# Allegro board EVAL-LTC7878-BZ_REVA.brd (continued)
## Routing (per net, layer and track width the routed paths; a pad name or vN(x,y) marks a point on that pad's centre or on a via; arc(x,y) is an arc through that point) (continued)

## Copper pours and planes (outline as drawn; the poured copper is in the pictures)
SGND on TOP: 89.74,137.54 89.77,137.53 89.79,137.49 89.79,136.83 89.77,136.79 89.74,136.78 88.57,136.78 88.53,136.79 88.52,136.83 88.52,137.49 88.53,137.53 88.57,137.54
SGND on TOP: 89.74,15.62 89.77,15.61 89.79,15.57 89.79,14.91 89.77,14.87 89.74,14.86 88.57,14.86 88.53,14.87 88.52,14.91 88.52,15.57 88.53,15.61 88.57,15.62
SGND on TOP: 102.58,72.26 104.43,72.26
SGND on TOP: 103.3,10.67 103.27,10.68 103.25,10.72 103.25,13.92 103.27,13.96 103.3,13.97 104.47,13.97 104.51,13.96 104.52,13.92 104.52,13.26 104.51,13.22 104.47,13.21 104.06,13.21 104.03,13.19 104.01,13.16 104.01,10.72 104,10.68 103.96,10.67
SGND on TOP: 98.98,133.84 98.99,133.85 99.01,133.86 99.39,133.86 99.43,133.84 99.44,133.81 99.44,132 99.43,131.97 99.39,131.95 98.73,131.95 98.69,131.97 98.68,132 98.68,133.53 98.68,133.54 98.69,133.56
SGND on TOP: 102.58,11.3 104.43,11.3
SGND on TOP: 103.25,141.94 103.27,141.97 103.3,141.99 105.23,141.99 105.27,141.97 105.28,141.94 105.28,139.19 104.14,139.19 104.14,137.16 103.3,137.16 103.27,137.18 103.25,137.21 103.25,139.9 103.27,139.94 103.3,139.95 104.9,139.95 104.9,141.22 103.3,141.22 103.27,141.24 103.25,141.28
SGND on TOP: 96.65,72.85 96.66,72.88 96.7,72.9 97.36,72.9 97.39,72.88 97.41,72.85 97.41,71.68 97.39,71.64 97.36,71.63 96.7,71.63 96.66,71.64 96.65,71.68
SGND on TOP: 103.3,254.51 103.27,254.52 103.25,254.56 103.25,257.76 103.27,257.8 103.3,257.81 104.47,257.81 104.51,257.8 104.52,257.76 104.52,257.1 104.51,257.06 104.47,257.05 104.06,257.05 104.03,257.03 104.01,257 104.01,254.56 104,254.52 103.96,254.51
SGND on TOP: 98.98,194.8 98.99,194.81 99.01,194.82 99.39,194.82 99.43,194.8 99.44,194.77 99.44,192.96 99.43,192.93 99.39,192.91 98.73,192.91 98.69,192.93 98.68,192.96 98.68,194.49 98.68,194.5 98.69,194.52
SGND on TOP: 103.25,80.98 103.27,81.01 103.3,81.03 105.23,81.03 105.27,81.01 105.28,80.98 105.28,78.23 104.14,78.23 104.14,76.2 103.3,76.2 103.27,76.22 103.25,76.25 103.25,78.94 103.27,78.98 103.3,78.99 104.9,78.99 104.9,80.26 103.3,80.26 103.27,80.28 103.25,80.32
SGND on TOP: 90.88,135.38 90.92,135.37 90.93,135.33 90.93,134.54 90.92,134.51 90.88,134.49 89.2,134.49 89.17,134.51 89.15,134.54 89.15,135.33 89.17,135.37 89.2,135.38
SGND on TOP: 96.65,255.73 96.66,255.76 96.7,255.78 97.36,255.78 97.39,255.76 97.41,255.73 97.41,254.56 97.39,254.52 97.36,254.51 96.7,254.51 96.66,254.52 96.65,254.56
SGND on TOP: 89.74,259.46 89.77,259.45 89.79,259.41 89.79,258.75 89.77,258.71 89.74,258.7 88.57,258.7 88.53,258.71 88.52,258.75 88.52,259.41 88.53,259.45 88.57,259.46
SGND on TOP: 96.65,11.89 96.66,11.92 96.7,11.94 97.36,11.94 97.39,11.92 97.41,11.89 97.41,10.72 97.39,10.68 97.36,10.67 96.7,10.67 96.66,10.68 96.65,10.72
SGND on TOP: 98.98,11.92 98.99,11.93 99.01,11.94 99.39,11.94 99.43,11.92 99.44,11.89 99.44,10.08 99.43,10.05 99.39,10.03 98.73,10.03 98.69,10.05 98.68,10.08 98.68,11.61 98.68,11.62 98.69,11.64
SGND on TOP: 90.88,257.3 90.92,257.29 90.93,257.25 90.93,256.46 90.92,256.43 90.88,256.41 89.2,256.41 89.17,256.43 89.15,256.46 89.15,257.25 89.17,257.29 89.2,257.3
SGND on TOP: 103.25,263.86 103.27,263.89 103.3,263.91 105.23,263.91 105.27,263.89 105.28,263.86 105.28,261.11 104.14,261.11 104.14,259.08 103.3,259.08 103.27,259.1 103.25,259.13 103.25,261.82 103.27,261.86 103.3,261.87 104.6,261.87 104.63,261.89 104.65,261.92 104.65,263.09 104.63,263.13 104.6,263.14 103.3,263.14 103.27,263.16 103.25,263.2
SGND on TOP: 89.74,76.58 89.77,76.57 89.79,76.53 89.79,75.87 89.77,75.83 89.74,75.82 88.57,75.82 88.53,75.83 88.52,75.87 88.52,76.53 88.53,76.57 88.57,76.58
SGND on TOP: 103.3,193.55 103.27,193.56 103.25,193.6 103.25,196.8 103.27,196.84 103.3,196.85 104.47,196.85 104.51,196.84 104.52,196.8 104.52,196.14 104.51,196.1 104.47,196.09 104.06,196.09 104.03,196.07 104.01,196.04 104.01,193.6 104,193.56 103.96,193.55
SGND on TOP: 102.58,255.14 104.43,255.14
SGND on TOP: 96.65,194.77 96.66,194.8 96.7,194.82 97.36,194.82 97.39,194.8 97.41,194.77 97.41,193.6 97.39,193.56 97.36,193.55 96.7,193.55 96.66,193.56 96.65,193.6
SGND on TOP: 90.88,13.46 90.92,13.45 90.93,13.41 90.93,12.62 90.92,12.59 90.88,12.57 89.2,12.57 89.17,12.59 89.15,12.62 89.15,13.41 89.17,13.45 89.2,13.46
SGND on TOP: 98.98,72.88 98.99,72.89 99.01,72.9 99.39,72.9 99.43,72.88 99.44,72.85 99.44,71.04 99.43,71.01 99.39,70.99 98.73,70.99 98.69,71.01 98.68,71.04 98.68,72.57 98.68,72.58 98.69,72.6
SGND on TOP: 102.58,133.22 104.43,133.22
SGND on TOP: 103.3,132.59 103.27,132.6 103.25,132.64 103.25,135.84 103.27,135.88 103.3,135.89 104.47,135.89 104.51,135.88 104.52,135.84 104.52,135.18 104.51,135.14 104.47,135.13 104.06,135.13 104.03,135.11 104.01,135.08 104.01,132.64 104,132.6 103.96,132.59
SGND on TOP: 89.74,198.5 89.77,198.49 89.79,198.45 89.79,197.79 89.77,197.75 89.74,197.74 88.57,197.74 88.53,197.75 88.52,197.79 88.52,198.45 88.53,198.49 88.57,198.5
SGND on TOP: 98.98,255.76 98.99,255.77 99.01,255.78 99.39,255.78 99.43,255.76 99.44,255.73 99.44,253.92 99.43,253.89 99.39,253.87 98.73,253.87 98.69,253.89 98.68,253.92 98.68,255.45 98.68,255.46 98.69,255.48
SGND on TOP: 103.25,202.9 103.27,202.93 103.3,202.95 105.23,202.95 105.27,202.93 105.28,202.9 105.28,200.15 104.14,200.15 104.14,198.12 103.3,198.12 103.27,198.14 103.25,198.17 103.25,200.86 103.27,200.9 103.3,200.91 104.9,200.91 104.9,202.18 103.3,202.18 103.27,202.2 103.25,202.24
SGND on TOP: 102.58,194.18 104.43,194.18
SGND on TOP: 90.88,74.42 90.92,74.41 90.93,74.37 90.93,73.58 90.92,73.55 90.88,73.53 89.2,73.53 89.17,73.55 89.15,73.58 89.15,74.37 89.17,74.41 89.2,74.42
SGND on TOP: 90.88,196.34 90.92,196.33 90.93,196.29 90.93,195.5 90.92,195.47 90.88,195.45 89.2,195.45 89.17,195.47 89.15,195.5 89.15,196.29 89.17,196.33 89.2,196.34
SGND on TOP: 103.25,20.02 103.27,20.05 103.3,20.07 105.23,20.07 105.27,20.05 105.28,20.02 105.28,17.27 104.14,17.27 104.14,15.24 103.3,15.24 103.27,15.26 103.25,15.29 103.25,17.98 103.27,18.02 103.3,18.03 104.9,18.03 104.9,19.3 103.3,19.3 103.27,19.32 103.25,19.36
SGND on TOP: 96.65,133.81 96.66,133.84 96.7,133.86 97.36,133.86 97.39,133.84 97.41,133.81 97.41,132.64 97.39,132.6 97.36,132.59 96.7,132.59 96.66,132.6 96.65,132.64
SGND on TOP: 103.3,71.63 103.27,71.64 103.25,71.68 103.25,74.88 103.27,74.92 103.3,74.93 104.47,74.93 104.51,74.92 104.52,74.88 104.52,74.22 104.51,74.18 104.47,74.17 104.06,74.17 104.03,74.15 104.01,74.12 104.01,71.68 104,71.64 103.96,71.63
SGND on BOTTOM: 108.97,84.33 108.97,66.55 83.57,66.55 83.57,84.33
SGND on BOTTOM: 108.97,23.24 108.97,5.71 83.57,5.71 83.57,23.24
SGND on BOTTOM: 109.09,188.59 83.57,188.59 83.57,206.12 109.09,206.12
SGND on BOTTOM: 109.09,249.56 83.57,249.56 83.57,267.21 109.09,267.21
SGND on BOTTOM: 108.97,127.64 83.44,127.64 83.44,145.29 108.97,145.29
SGND on LAYER_2: 82.3,307.47 82.3,8.64 113.41,8.64 113.41,307.47
SGND on LAYER_3: 109.09,249.56 83.57,249.56 83.57,269.88 109.09,269.88
SGND on LAYER_3: 83.44,127.64 83.44,147.96 108.97,147.96 108.97,127.64
SGND on LAYER_3: 109.09,188.72 83.57,188.72 83.57,208.91 109.09,208.91
SGND on LAYER_3: 83.57,5.71 83.57,26.04 108.97,26.04 108.97,5.71
SGND on LAYER_3: 83.57,66.67 83.57,87 108.97,87 108.97,66.67
SGND on LAYER_4: 95.25,20.83 94.11,19.68 94.11,16.89 97.79,16.89 98.04,17.14 98.04,20.83
SGND on LAYER_4: 95.89,265.05 94.11,263.27 94.11,260.73 97.85,260.73 98.04,260.92 98.04,265.05
SGND on LAYER_4: 95.63,143 94.11,141.48 94.11,138.81 97.79,138.81 98.04,139.06 98.04,143
SGND on LAYER_4: 95.89,203.96 94.23,202.31 94.23,199.77 97.79,199.77 98.04,200.03 98.04,203.96
SGND on LAYER_4: 95.89,82.17 94.11,80.39 94.11,77.85 97.79,77.85 98.04,78.11 98.04,82.17
SGND on LAYER_5: 114.3,273.62 114.3,10.6 89.73,10.6 89.73,273.62
SGND on LAYER_6: 100.33,259.71 92.84,259.71 92.84,268.86 100.33,268.86
SGND on LAYER_6: 100.33,207.9 100.33,198.75 92.84,198.75 92.84,207.9
SGND on LAYER_6: 100.33,15.88 92.84,15.88 92.84,25.02 100.33,25.02
SGND on LAYER_6: 100.33,146.81 100.33,137.79 92.84,137.79 92.84,146.81
SGND on LAYER_6: 100.33,86.11 100.33,77.22 92.84,77.22 92.84,86.11
VIN on TOP: 88.27,13.41 88.28,13.45 88.32,13.46 88.72,13.46 88.76,13.45 88.77,13.41 88.77,12.24 88.76,12.21 88.72,12.19 88.32,12.19 88.28,12.21 88.27,12.24
VIN on TOP: 88.03,143.64 88.01,143.64 88,143.65 87.9,143.75 87.89,143.77 87.88,143.79 87.88,144.35 87.9,144.38 87.93,144.4 89.1,144.4 89.14,144.38 89.15,144.35 89.15,143.69 89.14,143.65 89.1,143.64
VIN on TOP: 88.27,74.37 88.28,74.41 88.32,74.42 88.72,74.42 88.76,74.41 88.77,74.37 88.77,73.2 88.76,73.17 88.72,73.15 88.32,73.15 88.28,73.17 88.27,73.2
VIN on TOP: 88.03,204.6 88.01,204.6 88,204.61 87.9,204.71 87.89,204.73 87.88,204.75 87.88,205.31 87.9,205.34 87.93,205.36 89.1,205.36 89.14,205.34 89.15,205.31 89.15,204.65 89.14,204.61 89.1,204.6
VIN on TOP: 88.27,257.25 88.28,257.29 88.32,257.3 88.72,257.3 88.76,257.29 88.77,257.25 88.77,256.08 88.76,256.05 88.72,256.03 88.32,256.03 88.28,256.05 88.27,256.08
VIN on TOP: 88.27,196.29 88.28,196.33 88.32,196.34 88.72,196.34 88.76,196.33 88.77,196.29 88.77,195.12 88.76,195.09 88.72,195.07 88.32,195.07 88.28,195.09 88.27,195.12
VIN on TOP: 88.03,82.68 88.01,82.68 88,82.69 87.9,82.79 87.89,82.81 87.88,82.83 87.88,83.39 87.9,83.42 87.93,83.44 89.1,83.44 89.14,83.42 89.15,83.39 89.15,82.73 89.14,82.69 89.1,82.68
VIN on TOP: 88.27,135.33 88.28,135.37 88.32,135.38 88.72,135.38 88.76,135.37 88.77,135.33 88.77,134.16 88.76,134.13 88.72,134.11 88.32,134.11 88.28,134.13 88.27,134.16
VIN on TOP: 125.35,129.54 125.35,126.11 128.91,126.11 130.05,127.25 132.84,127.25 133.48,127.89 134.37,127.89 134.62,128.14 136.4,128.14 136.46,128.21 136.46,128.71 136.4,128.78 135.76,128.78 135,129.54
VIN on TOP: 14.48,305.56 79.12,305.56 79.12,287.02 39.5,287.02 39.5,244.6 79.12,244.6 79.12,226.06 39.5,226.06 39.5,183.64 79.12,183.64 79.12,165.1 39.5,165.1 39.5,122.68 79.12,122.68 79.12,104.14 39.5,104.14 39.5,61.72 79.12,61.72 79.12,43.18 39.5,43.18 39.5,43.15 14.91,43.15 14.91,152.65 2.67,152.65 2.67,200.66 14.48,200.66
VIN on TOP: 88.03,21.72 88.01,21.72 88,21.73 87.9,21.83 87.89,21.85 87.88,21.87 87.88,22.43 87.9,22.46 87.93,22.48 89.1,22.48 89.14,22.46 89.15,22.43 89.15,21.77 89.14,21.73 89.1,21.72
VIN on TOP: 88.03,265.56 88.01,265.56 88,265.57 87.9,265.67 87.89,265.69 87.88,265.71 87.88,266.27 87.9,266.3 87.93,266.32 89.1,266.32 89.14,266.3 89.15,266.27 89.15,265.61 89.14,265.57 89.1,265.56
VIN on BOTTOM: 14.48,305.56 79.07,305.56 79.11,305.55 79.12,305.51 79.12,287.07 79.11,287.03 79.07,287.02 39.5,287.02 39.5,244.6 79.12,244.6 79.12,226.11 79.11,226.07 79.07,226.06 39.5,226.06 39.5,183.64 79.12,183.64 79.12,165.15 79.11,165.11 79.07,165.1 39.5,165.1 39.5,122.68 79.12,122.68 79.12,104.14 39.5,104.14 39.5,61.72 79.12,61.72 79.12,43.18 39.5,43.18 39.5,43.15 14.91,43.15 14.91,152.65 2.67,152.65 2.67,200.66 14.48,200.66
VIN on LAYER_2: 2.54,202.56 2.54,150.5 13.97,150.5 13.97,8.64 79.38,8.64 79.38,31.75 71.12,31.75 71.12,41.91 79.38,41.91 79.38,92.71 71.12,92.71 71.12,102.23 79.38,102.23 79.38,153.67 70.99,153.67 70.99,163.19 79.38,163.19 79.38,214.63 70.99,214.63 70.99,224.16 79.38,224.16 79.38,275.59 71.12,275.59 71.12,285.12 79.38,285.12 79.38,307.47 13.97,307.47 13.97,202.56
VIN on LAYER_3, LAYER_7: 79.38,225.3 79.38,233.93 71.63,233.93 71.63,225.3
VIN on LAYER_3, LAYER_7: 79.38,42.42 79.38,51.05 71.63,51.05 71.63,42.42
VIN on LAYER_3, LAYER_7: 79.38,286.26 79.38,294.89 71.63,294.89 71.63,286.26
VIN on LAYER_3, LAYER_7: 79.38,103.38 79.38,112.01 71.63,112.01 71.63,103.38
VIN on LAYER_3, LAYER_7: 79.38,164.34 79.38,172.97 71.63,172.97 71.63,164.34
VIN on LAYER_4, LAYER_5, LAYER_6: 79.38,163.19 79.38,172.21 71.63,172.21 71.63,163.19
VIN on LAYER_4, LAYER_5, LAYER_6: 79.38,224.16 79.38,233.17 71.63,233.17 71.63,224.16
VIN on LAYER_4, LAYER_5, LAYER_6: 79.38,102.23 79.38,111.25 71.63,111.25 71.63,102.23
VIN on LAYER_4, LAYER_5, LAYER_6: 79.38,285.12 79.38,294.13 71.63,294.13 71.63,285.12
VIN on LAYER_4, LAYER_5, LAYER_6: 79.38,41.27 79.38,50.29 71.63,50.29 71.63,41.27
DRVCC_1 on TOP: 91.26,263.21 91.3,263.19 91.31,263.16 91.31,262.62 91.3,262.59 91.26,262.57 90.09,262.57 90.06,262.59 90.04,262.62 90.04,263.16 90.06,263.19 90.09,263.21
DRVCC_1 on TOP: 91.26,268.1 91.3,268.08 91.31,268.05 91.31,267.39 91.3,267.35 91.26,267.33 89.84,267.33 89.8,267.35 89.79,267.39 89.79,268.05 89.8,268.08 89.84,268.1
DRVCC_1 on TOP: 77.31,266.95 79.16,266.95
DRVCC_1 on TOP: 92.02,255.4 92.06,255.38 92.08,255.35 92.08,254.69 92.06,254.65 92.02,254.63 90.86,254.63 90.82,254.65 90.81,254.69 90.81,255.35 90.82,255.38 90.86,255.4
DRVCC_2 on TOP: 77.31,205.99 79.16,205.99
DRVCC_2 on TOP: 91.26,207.14 91.3,207.12 91.31,207.09 91.31,206.43 91.3,206.39 91.26,206.38 89.84,206.38 89.8,206.39 89.79,206.43 89.79,207.09 89.8,207.12 89.84,207.14
DRVCC_2 on TOP: 91.26,202.25 91.3,202.23 91.31,202.2 91.31,201.66 91.3,201.63 91.26,201.61 90.09,201.61 90.06,201.63 90.04,201.66 90.04,202.2 90.06,202.23 90.09,202.25
DRVCC_2 on TOP: 92.02,194.44 92.06,194.42 92.08,194.39 92.08,193.73 92.06,193.69 92.02,193.68 90.86,193.68 90.82,193.69 90.81,193.73 90.81,194.39 90.82,194.42 90.86,194.44
DRVCC_3 on TOP: 91.26,146.18 91.3,146.16 91.31,146.13 91.31,145.47 91.3,145.43 91.26,145.41 89.84,145.41 89.8,145.43 89.79,145.47 89.79,146.13 89.8,146.16 89.84,146.18
DRVCC_3 on TOP: 92.02,133.48 92.06,133.46 92.08,133.43 92.08,132.77 92.06,132.73 92.02,132.72 90.86,132.72 90.82,132.73 90.81,132.77 90.81,133.43 90.82,133.46 90.86,133.48
DRVCC_3 on TOP: 77.31,145.03 79.16,145.03
DRVCC_3 on TOP: 91.26,141.29 91.3,141.27 91.31,141.24 91.31,140.7 91.3,140.67 91.26,140.65 90.09,140.65 90.06,140.67 90.04,140.7 90.04,141.24 90.06,141.27 90.09,141.29
DRVCC_4 on TOP: 91.26,85.22 91.3,85.2 91.31,85.17 91.31,84.51 91.3,84.47 91.26,84.45 89.84,84.45 89.8,84.47 89.79,84.51 89.79,85.17 89.8,85.2 89.84,85.22
DRVCC_4 on TOP: 92.02,72.52 92.06,72.5 92.08,72.47 92.08,71.81 92.06,71.77 92.02,71.75 90.86,71.75 90.82,71.77 90.81,71.81 90.81,72.47 90.82,72.5 90.86,72.52
DRVCC_4 on TOP: 77.31,84.07 79.16,84.07
DRVCC_4 on TOP: 91.26,80.33 91.3,80.31 91.31,80.28 91.31,79.74 91.3,79.71 91.26,79.69 90.09,79.69 90.06,79.71 90.04,79.74 90.04,80.28 90.06,80.31 90.09,80.33
DRVCC_5 on TOP: 91.26,24.26 91.3,24.24 91.31,24.21 91.31,23.55 91.3,23.51 91.26,23.5 89.84,23.5 89.8,23.51 89.79,23.55 89.79,24.21 89.8,24.24 89.84,24.26
DRVCC_5 on TOP: 77.31,23.11 79.16,23.11
DRVCC_5 on TOP: 91.26,19.37 91.3,19.35 91.31,19.32 91.31,18.78 91.3,18.75 91.26,18.73 90.09,18.73 90.06,18.75 90.04,18.78 90.04,19.32 90.06,19.35 90.09,19.37
DRVCC_5 on TOP: 92.02,11.56 92.06,11.54 92.08,11.51 92.08,10.85 92.06,10.81 92.02,10.79 90.86,10.79 90.82,10.81 90.81,10.85 90.81,11.51 90.82,11.54 90.86,11.56
GROUND on TOP: 1.27,316.23 184.15,316.23 184.15,1.27 1.27,1.27 ; 10 cut-outs
GROUND on BOTTOM, LAYER_2, LAYER_4, LAYER_5, LAYER_6, LAYER_7: 1.27,316.23 184.15,316.23 184.15,1.27 1.27,1.27
GROUND on LAYER_3: 1.27,316.23 184.15,316.23 184.15,1.27 1.27,1.27
INTVCC_1 on TOP: 95.63,255.73 95.65,255.76 95.68,255.78 96.34,255.78 96.38,255.76 96.39,255.73 96.39,254.94 96.38,254.9 96.34,254.89 95.3,254.89 95.26,254.9 95.25,254.94 95.25,255.47 95.26,255.51 95.3,255.52 95.58,255.52 95.62,255.54 95.63,255.57
INTVCC_1 on TOP: 77.18,258.32 79.03,258.32
INTVCC_1 on TOP: 105.66,260.81 105.68,260.84 105.72,260.86 106.5,260.86 106.54,260.84 106.55,260.81 106.55,259.19 106.54,259.16 106.5,259.14 105.72,259.14 105.68,259.16 105.66,259.19
INTVCC_2 on TOP: 77.18,197.36 79.03,197.36
INTVCC_2 on TOP: 105.66,199.85 105.68,199.88 105.72,199.9 106.5,199.9 106.54,199.88 106.55,199.85 106.55,198.23 106.54,198.2 106.5,198.18 105.72,198.18 105.68,198.2 105.66,198.23
INTVCC_2 on TOP: 95.63,194.77 95.65,194.8 95.68,194.82 96.34,194.82 96.38,194.8 96.39,194.77 96.39,193.98 96.38,193.94 96.34,193.93 95.3,193.93 95.26,193.94 95.25,193.98 95.25,194.51 95.26,194.55 95.3,194.56 95.58,194.56 95.62,194.58 95.63,194.61
INTVCC_3 on TOP: 77.18,136.4 79.03,136.4
INTVCC_3 on TOP: 105.66,138.89 105.68,138.92 105.72,138.94 106.5,138.94 106.54,138.92 106.55,138.89 106.55,137.27 106.54,137.24 106.5,137.22 105.72,137.22 105.68,137.24 105.66,137.27
INTVCC_3 on TOP: 95.63,133.81 95.65,133.84 95.68,133.86 96.34,133.86 96.38,133.84 96.39,133.81 96.39,133.02 96.38,132.98 96.34,132.97 95.3,132.97 95.26,132.98 95.25,133.02 95.25,133.55 95.26,133.59 95.3,133.6 95.58,133.6 95.62,133.62 95.63,133.65
INTVCC_4 on TOP: 105.66,77.93 105.68,77.96 105.72,77.98 106.5,77.98 106.54,77.96 106.55,77.93 106.55,76.31 106.54,76.28 106.5,76.26 105.72,76.26 105.68,76.28 105.66,76.31
INTVCC_4 on TOP: 77.18,75.44 79.03,75.44
INTVCC_4 on TOP: 95.63,72.85 95.65,72.88 95.68,72.9 96.34,72.9 96.38,72.88 96.39,72.85 96.39,72.06 96.38,72.02 96.34,72.01 95.3,72.01 95.26,72.02 95.25,72.06 95.25,72.59 95.26,72.63 95.3,72.64 95.58,72.64 95.62,72.66 95.63,72.69
INTVCC_5 on TOP: 77.18,14.48 79.03,14.48
INTVCC_5 on TOP: 105.66,16.97 105.68,17 105.72,17.02 106.5,17.02 106.54,17 106.55,16.97 106.55,15.35 106.54,15.32 106.5,15.3 105.72,15.3 105.68,15.32 105.66,15.35
INTVCC_5 on TOP: 95.63,11.89 95.65,11.92 95.68,11.94 96.34,11.94 96.38,11.92 96.39,11.89 96.39,11.1 96.38,11.06 96.34,11.05 95.3,11.05 95.26,11.06 95.25,11.1 95.25,11.63 95.26,11.67 95.3,11.68 95.58,11.68 95.62,11.7 95.63,11.73
ITH_1 on TOP: 115.23,252.73 117.18,252.73
ITH_1 on TOP: 97.66,255.73 97.68,255.76 97.71,255.78 98.37,255.78 98.41,255.76 98.42,255.73 98.42,253.92 98.41,253.89 98.37,253.87 97.71,253.87 97.68,253.89 97.66,253.92
ITH_1 on TOP: 98.68,257.12 98.69,257.16 98.73,257.18 99.39,257.18 99.43,257.16 99.44,257.12 99.44,256.08 99.43,256.05 99.39,256.03 98.73,256.03 98.69,256.05 98.68,256.08
ITH_2 on TOP: 97.66,194.77 97.68,194.8 97.71,194.82 98.37,194.82 98.41,194.8 98.42,194.77 98.42,192.96 98.41,192.93 98.37,192.91 97.71,192.91 97.68,192.93 97.66,192.96
ITH_2 on TOP: 115.23,191.77 117.18,191.77
ITH_2 on TOP: 98.68,196.16 98.69,196.2 98.73,196.22 99.39,196.22 99.43,196.2 99.44,196.16 99.44,195.12 99.43,195.09 99.39,195.07 98.73,195.07 98.69,195.09 98.68,195.12
ITH_3 on TOP: 98.68,135.2 98.69,135.24 98.73,135.25 99.39,135.25 99.43,135.24 99.44,135.2 99.44,134.16 99.43,134.13 99.39,134.11 98.73,134.11 98.69,134.13 98.68,134.16
ITH_3 on TOP: 115.23,130.18 117.18,130.18
ITH_3 on TOP: 97.66,133.81 97.68,133.84 97.71,133.86 98.37,133.86 98.41,133.84 98.42,133.81 98.42,132 98.41,131.97 98.37,131.95 97.71,131.95 97.68,131.97 97.66,132
ITH_4 on TOP: 97.66,72.85 97.68,72.88 97.71,72.9 98.37,72.9 98.41,72.88 98.42,72.85 98.42,71.04 98.41,71.01 98.37,70.99 97.71,70.99 97.68,71.01 97.66,71.04
ITH_4 on TOP: 98.68,74.24 98.69,74.28 98.73,74.3 99.39,74.3 99.43,74.28 99.44,74.24 99.44,73.2 99.43,73.17 99.39,73.15 98.73,73.15 98.69,73.17 98.68,73.2
ITH_4 on TOP: 115.23,69.22 117.18,69.22
ITH_5 on TOP: 97.66,11.89 97.68,11.92 97.71,11.94 98.37,11.94 98.41,11.92 98.42,11.89 98.42,10.08 98.41,10.05 98.37,10.03 97.71,10.03 97.68,10.05 97.66,10.08
ITH_5 on TOP: 98.68,13.28 98.69,13.32 98.73,13.34 99.39,13.34 99.43,13.32 99.44,13.28 99.44,12.24 99.43,12.21 99.39,12.19 98.73,12.19 98.69,12.21 98.68,12.24
ITH_5 on TOP: 115.23,10.16 117.18,10.16
RUN_1 on TOP: 86.61,258.39 86.63,258.43 86.66,258.44 88.26,258.44 90.88,258.44 90.92,258.43 90.93,258.39 90.93,257.61 90.92,257.57 90.88,257.56 86.87,257.56 86.66,257.56 86.63,257.57 86.61,257.61
RUN_2 on TOP: 86.61,197.43 86.63,197.47 86.66,197.49 88.26,197.49 90.88,197.48 90.92,197.47 90.93,197.43 90.93,196.65 90.92,196.61 90.88,196.6 86.87,196.6 86.66,196.6 86.63,196.61 86.61,196.65
RUN_2 on TOP: 87.12,257.25 87.14,257.29 87.17,257.3 87.83,257.3 87.87,257.29 87.88,257.25 87.88,256.08 87.87,256.05 87.83,256.03 87.17,256.03 87.14,256.05 87.12,256.08
RUN_3 on TOP: 87.12,196.29 87.14,196.33 87.17,196.34 87.83,196.34 87.87,196.33 87.88,196.29 87.88,195.12 87.87,195.09 87.83,195.07 87.17,195.07 87.14,195.09 87.12,195.12
RUN_3 on TOP: 86.61,136.47 86.63,136.51 86.66,136.53 88.26,136.53 90.88,136.52 90.92,136.51 90.93,136.47 90.93,135.69 90.92,135.65 90.88,135.64 86.87,135.64 86.66,135.64 86.63,135.65 86.61,135.69
RUN_4 on TOP: 87.12,135.33 87.14,135.37 87.17,135.38 87.83,135.38 87.87,135.37 87.88,135.33 87.88,134.16 87.87,134.13 87.83,134.11 87.17,134.11 87.14,134.13 87.12,134.16
RUN_4 on TOP: 86.61,75.51 86.63,75.55 86.66,75.56 88.26,75.56 90.88,75.56 90.92,75.55 90.93,75.51 90.93,74.73 90.92,74.69 90.88,74.68 86.87,74.68 86.66,74.68 86.63,74.69 86.61,74.73
RUN_5 on TOP: 87.12,74.37 87.14,74.41 87.17,74.42 87.83,74.42 87.87,74.41 87.88,74.37 87.88,73.2 87.87,73.17 87.83,73.15 87.17,73.15 87.14,73.17 87.12,73.2
SS_1 on TOP: 115.23,248.28 117.18,248.28
SS_1 on TOP: 96.65,257.12 96.66,257.16 96.7,257.18 97.36,257.18 97.39,257.16 97.41,257.12 97.41,256.08 97.39,256.05 97.36,256.03 96.7,256.03 96.66,256.05 96.65,256.08
SS_2 on TOP: 96.65,196.16 96.66,196.2 96.7,196.22 97.36,196.22 97.39,196.2 97.41,196.16 97.41,195.12 97.39,195.09 97.36,195.07 96.7,195.07 96.66,195.09 96.65,195.12
SS_2 on TOP: 115.23,186.69 117.18,186.69
SS_3 on TOP: 96.65,135.2 96.66,135.24 96.7,135.25 97.36,135.25 97.39,135.24 97.41,135.2 97.41,134.16 97.39,134.13 97.36,134.11 96.7,134.11 96.66,134.13 96.65,134.16
SS_3 on TOP: 115.23,125.09 117.18,125.09
SS_4 on TOP: 96.65,74.24 96.66,74.28 96.7,74.3 97.36,74.3 97.39,74.28 97.41,74.24 97.41,73.2 97.39,73.17 97.36,73.15 96.7,73.15 96.66,73.17 96.65,73.2
SS_4 on TOP: 115.23,64.14 117.18,64.14
SS_5 on TOP: 115.23,5.08 117.18,5.08
SS_5 on TOP: 96.65,13.28 96.66,13.32 96.7,13.34 97.36,13.34 97.39,13.32 97.41,13.28 97.41,12.24 97.39,12.21 97.36,12.19 96.7,12.19 96.66,12.21 96.65,12.24
UNNAMED_1_ADLTC7878V2_I139_BG1 on TOP: 73.1,277.75 73.14,277.73 73.15,277.7 73.15,276.53 73.14,276.49 73.1,276.48 72.19,276.48 72.15,276.49 72.14,276.53 72.14,277.7 72.15,277.73 72.19,277.75
UNNAMED_1_ADLTC7878V2_I139_BG2 on TOP: 106.48,276.48 106.44,276.49 106.43,276.53 106.43,277.7 106.44,277.73 106.48,277.75 107.14,277.75 107.17,277.73 107.19,277.7 107.19,276.53 107.17,276.49 107.14,276.48
UNNAMED_1_ADLTC7878V2_I139_BOOST1 on TOP: 92.2,268.05 92.22,268.08 92.25,268.1 93.58,268.1 93.6,268.09 93.61,268.08 93.71,267.98 93.73,267.97 93.75,267.97 94.49,267.97 94.51,267.97 94.53,267.96 94.73,267.76 94.74,267.74 94.74,267.72 94.74,267.13 94.73,267.1 94.69,267.08 94.13,267.08 94.11,267.08 94.09,267.1 93.87,267.32 93.85,267.33 93.83,267.33 92.25,267.33 92.22,267.35 92.2,267.39
UNNAMED_1_ADLTC7878V2_I139_CSN on TOP: 102.86,268.22 104.66,268.22
UNNAMED_1_ADLTC7878V2_I139_CSP on TOP: 104.27,265.94 104.27,264.16 102.11,264.16 101.73,264.54 101.73,265.18 102.11,265.56 103.38,265.56 103.38,265.94
UNNAMED_1_ADLTC7878V2_I139_EXTVCC on TOP: 89.41,262.2 89.42,262.24 89.46,262.25 91.13,262.25 91.15,262.25 91.17,262.24 91.3,262.11 91.31,262.1 91.31,262.08 91.31,261.37 90.81,260.86 90.81,259.71 90.04,259.71 90.04,260.73 89.41,260.73
UNNAMED_1_ADLTC7878V2_I139_EXTVCC on TOP: 77.31,263.14 79.16,263.14
UNNAMED_1_ADLTC7878V2_I139_ISNSD on TOP: 95.83,269.24 95.87,269.23 95.89,269.19 95.89,268.15 95.87,268.11 95.83,268.1 95.53,268.1 95.51,268.1 95.49,268.11 95.07,268.53 95.06,268.54 95.06,268.56 95.06,269.19 95.07,269.23 95.11,269.24
UNNAMED_1_ADLTC7878V2_I139_ITHB on TOP: 97.66,257.12 97.68,257.16 97.71,257.18 98.37,257.18 98.41,257.16 98.42,257.12 98.42,256.31 98.42,256.29 98.41,256.28 98.18,256.05 98.17,256.04 98.15,256.03 97.71,256.03 97.68,256.05 97.66,256.08
UNNAMED_1_ADLTC7878V2_I139_PGOOD on TOP: 95.63,257.12 95.65,257.16 95.68,257.18 96.34,257.18 96.38,257.16 96.39,257.12 96.39,256.08 96.38,256.05 96.34,256.03 95.68,256.03 95.65,256.05 95.63,256.08
UNNAMED_1_ADLTC7878V2_I139_PGOOD on TOP: 77.18,254.63 79.03,254.63
UNNAMED_1_ADLTC7878V2_I139_SETCUR on TOP: 101.73,263.86 101.74,263.89 101.78,263.91 102.95,263.91 102.98,263.89 103,263.86 103,263.2 102.98,263.16 102.95,263.14 101.78,263.14 101.74,263.16 101.73,263.2
UNNAMED_1_ADLTC7878V2_I139_SW1 on TOP: 74.16,286.61 74.18,286.63 74.2,286.64 77.55,286.64 77.58,286.62 77.6,286.59 77.6,284.91 77.61,284.88 77.65,284.86 79.35,284.86 79.37,284.86 79.39,284.88 79.87,285.35 79.88,285.37 79.9,285.37 80.52,285.37 80.52,288.16 83.06,288.16 83.06,276.48 73.71,276.48 73.67,276.49 73.66,276.53 73.66,277.75 73.66,280.54 73.66,284.59 73.66,284.63 73.66,285.7 73.67,285.74 74.04,285.92 74.17,286.26 74.15,286.38 74.11,286.49 74.11,286.5 74.11,286.53
UNNAMED_1_ADLTC7878V2_I139_SW1 on TOP: 93.34,269.06 93.36,269.1 93.4,269.11 94.75,269.11 94.79,269.1 94.8,269.06 94.8,268.46 94.81,268.44 94.82,268.42 94.85,268.39 94.87,268.37 94.87,268.35 94.87,268.28 94.85,268.24 94.82,268.22 93.85,268.22 93.83,268.23 93.82,268.24 93.72,268.34 93.7,268.35 93.68,268.35 93.4,268.35 93.36,268.37 93.34,268.4
UNNAMED_1_ADLTC7878V2_I139_SW1 on TOP: 94.61,271.48 94.63,271.51 94.67,271.53 95.77,271.53 95.81,271.51 95.82,271.48 95.82,270.69 95.81,270.65 95.77,270.64 94.89,270.64 94.87,270.64 94.85,270.65 94.63,270.88 94.62,270.89 94.61,270.91
UNNAMED_1_ADLTC7878V2_I139_SW1 on BOTTOM: 75.31,286.59 75.33,286.62 75.36,286.64 78.71,286.64 78.73,286.63 78.75,286.61 78.8,286.53 78.8,286.5 78.8,286.49 78.75,286.38 78.74,286.26 78.89,285.9 79.25,285.75 79.42,285.78 79.57,285.87 79.59,285.88 79.63,285.88 82.8,285.88 82.8,276.53 82.79,276.49 82.75,276.48 73.84,276.48 73.8,276.49 73.79,276.53 73.79,284.81 73.8,284.85 73.84,284.86 75.26,284.86 75.3,284.88 75.31,284.91
UNNAMED_1_ADLTC7878V2_I139_SW1 on LAYER_2: 71.37,284.86 71.37,275.84 79.38,275.84 79.38,284.86
UNNAMED_1_ADLTC7878V2_I139_SW1 on LAYER_3, LAYER_7: 79.38,275.72 79.38,284.48 71.63,284.48 71.63,275.72
UNNAMED_1_ADLTC7878V2_I139_SW1 on LAYER_4, LAYER_5, LAYER_6: 79.38,275.72 79.38,284.73 71.63,284.73 71.63,275.72
UNNAMED_1_ADLTC7878V2_I139_SW2 on TOP: 99.44,270.56 99.43,270.52 99.39,270.51 98.73,270.51 98.69,270.52 98.68,270.56 98.68,271.98 98.69,272.02 98.73,272.03 99.39,272.03 99.43,272.02 99.44,271.98
UNNAMED_1_ADLTC7878V2_I139_SW2 on TOP: 113.28,293.88 113.28,284.99 115.32,284.99 115.32,281.31 113.54,281.31 113.54,281.31 113.28,281.31 113.28,279.78 106.05,279.78 106.05,276.48 97.41,276.48 97.41,293.88
UNNAMED_1_ADLTC7878V2_I139_SW2 on TOP: 94.52,257.17 94.54,257.18 95.33,257.18 95.36,257.16 95.38,257.12 95.38,255.83 95.36,255.79 95.33,255.78 94.54,255.78 94.5,255.79 94.49,255.83 94.49,257.12 94.49,257.14
UNNAMED_1_ADLTC7878V2_I139_SW2 on BOTTOM: 113.28,293.88 113.28,283.85 115.32,283.85 115.32,280.42 114.68,279.78 106.93,279.78 106.93,276.48 97.41,276.48 97.41,293.88
UNNAMED_1_ADLTC7878V2_I139_SW2 on LAYER_2: 105.28,288.93 105.28,279.91 113.28,279.91 113.28,288.93
UNNAMED_1_ADLTC7878V2_I139_SW2 on LAYER_3: 105.16,289.05 105.16,280.04 113.16,280.04 113.16,289.05
UNNAMED_1_ADLTC7878V2_I139_SW2 on LAYER_4: 107.82,285.24 107.82,277.88 113.28,277.88 113.28,285.24
UNNAMED_1_ADLTC7878V2_I139_SW2 on LAYER_5, LAYER_6, LAYER_7: 105.28,289.05 105.28,280.04 113.28,280.04 113.28,289.05
UNNAMED_1_ADLTC7878V2_I139_TG1 on TOP: 79.5,288.11 79.52,288.15 79.55,288.16 80.21,288.16 80.25,288.15 80.26,288.11 80.26,286.94 80.25,286.91 80.21,286.89 79.55,286.89 79.52,286.91 79.5,286.94
UNNAMED_1_ADLTC7878V2_I139_TG2 on TOP: 113.67,288.11 113.68,288.15 113.72,288.16 114.38,288.16 114.41,288.15 114.43,288.11 114.43,286.94 114.41,286.91 114.38,286.89 113.72,286.89 113.68,286.91 113.67,286.94
UNNAMED_1_ADLTC7878V2_I139_VOUT on TOP: 100.71,268.48 100.71,267.72 99.19,267.72 99.19,268.48
UNNAMED_1_CAP_I38_N1 on TOP: 97.66,253.57 97.68,253.6 97.71,253.62 99.39,253.62 99.43,253.6 99.44,253.57 99.44,252.78 99.43,252.74 99.39,252.73 97.71,252.73 97.68,252.74 97.66,252.78
UNNAMED_1_CAP_I100_N2 on TOP: 104.52,266.95 104.52,265.18 105.41,265.18 105.41,266.06 106.43,266.06 106.43,266.95
UNNAMED_1_CAP_I100_N2 on TOP: 105.78,268.22 107.58,268.22
UNNAMED_1_IND_I92_N1 on TOP: 96.2,271.86 96.22,271.89 96.25,271.91 96.85,271.91 96.89,271.89 96.9,271.86 96.9,270.82 96.89,270.78 96.85,270.76 96.25,270.76 96.22,270.78 96.2,270.82
UNNAMED_1_IND_I92_N1 on TOP: 95.76,293.88 95.76,276.48 83.31,276.48 83.31,293.88
UNNAMED_1_IND_I92_N1 on BOTTOM: 95.76,293.88 95.76,276.48 83.44,276.48 83.44,293.88
UNNAMED_1_NCTESTPAD_I113_N1 on TOP: 105.76,255.14 107.6,255.14
UNNAMED_1_RES_I73_N1 on TOP: 72.01,280.24 72.02,280.27 72.06,280.29 73.36,280.29 73.39,280.27 73.41,280.24 73.41,278.05 73.39,278.02 73.36,278 72.06,278 72.02,278.02 72.01,278.05
UNNAMED_1_RES_I87_N1 on TOP: 112.01,279.35 112.03,279.39 112.06,279.4 113.26,279.4 113.28,279.4 113.3,279.39 113.52,279.16 113.53,279.14 113.54,279.12 113.54,278.18 113.52,278.14 113.49,278.13 112.06,278.13 112.03,278.14 112.01,278.18
UNNAMED_1_RES_I115_N1 on TOP: 114.38,286.64 114.41,286.62 114.43,286.59 114.43,285.42 114.41,285.38 114.38,285.37 113.72,285.37 113.68,285.38 113.67,285.42 113.67,286.59 113.68,286.62 113.72,286.64
UNNAMED_1_RES_I115_N1 on TOP: 115.14,281.05 115.17,281.04 115.19,281 115.19,280.44 115.19,280.42 115.17,280.4 114.31,279.54 114.3,279.53 114.28,279.53 113.84,279.53 113.81,279.54 113.79,279.58 113.79,281 113.81,281.04 113.84,281.05
UNNAMED_2_ADLTC7878V2_I124_BG1 on TOP: 73.1,216.79 73.14,216.77 73.15,216.74 73.15,215.57 73.14,215.53 73.1,215.52 72.19,215.52 72.15,215.53 72.14,215.57 72.14,216.74 72.15,216.77 72.19,216.79
UNNAMED_2_ADLTC7878V2_I124_BG2 on TOP: 106.48,215.52 106.44,215.53 106.43,215.57 106.43,216.74 106.44,216.77 106.48,216.79 107.14,216.79 107.17,216.77 107.19,216.74 107.19,215.57 107.17,215.53 107.14,215.52
UNNAMED_2_ADLTC7878V2_I124_BOOST1 on TOP: 92.2,207.09 92.22,207.12 92.25,207.14 93.58,207.14 93.6,207.13 93.61,207.12 93.71,207.02 93.73,207.01 93.75,207.01 94.49,207.01 94.51,207.01 94.53,207 94.73,206.8 94.74,206.78 94.74,206.76 94.74,206.17 94.73,206.14 94.69,206.12 94.13,206.12 94.11,206.12 94.09,206.14 93.87,206.36 93.85,206.37 93.83,206.38 92.25,206.38 92.22,206.39 92.2,206.43
UNNAMED_2_ADLTC7878V2_I124_CSN on TOP: 102.86,207.26 104.66,207.26
UNNAMED_2_ADLTC7878V2_I124_CSP on TOP: 104.27,204.98 104.27,203.2 102.11,203.2 101.73,203.58 101.73,204.22 102.11,204.6 103.38,204.6 103.38,204.98
UNNAMED_2_ADLTC7878V2_I124_EXTVCC on TOP: 89.41,201.24 89.42,201.28 89.46,201.29 91.13,201.29 91.15,201.29 91.17,201.28 91.3,201.15 91.31,201.14 91.31,201.12 91.31,200.28 90.81,199.77 90.81,198.75 90.04,198.75 90.04,199.77 89.46,199.77 89.42,199.79 89.41,199.82
UNNAMED_2_ADLTC7878V2_I124_EXTVCC on TOP: 77.31,202.18 79.16,202.18
UNNAMED_2_ADLTC7878V2_I124_ISNSD on TOP: 95.83,208.28 95.87,208.27 95.89,208.23 95.89,207.19 95.87,207.15 95.83,207.14 95.53,207.14 95.51,207.14 95.49,207.15 95.07,207.57 95.06,207.58 95.06,207.6 95.06,208.23 95.07,208.27 95.11,208.28
UNNAMED_2_ADLTC7878V2_I124_ITHB on TOP: 97.66,196.16 97.68,196.2 97.71,196.22 98.37,196.22 98.41,196.2 98.42,196.16 98.42,195.35 98.42,195.33 98.41,195.32 98.18,195.09 98.17,195.08 98.15,195.07 97.71,195.07 97.68,195.09 97.66,195.12
UNNAMED_2_ADLTC7878V2_I124_MODE on TOP: 104.39,198.83 104.41,198.87 104.44,198.88 105.36,198.88 105.4,198.87 105.41,198.83 105.41,198.23 105.4,198.2 105.36,198.18 104.44,198.18 104.41,198.2 104.39,198.23
UNNAMED_2_ADLTC7878V2_I124_PGOOD on TOP: 77.18,193.68 79.03,193.68
UNNAMED_2_ADLTC7878V2_I124_PGOOD on TOP: 95.63,196.16 95.65,196.2 95.68,196.22 96.34,196.22 96.38,196.2 96.39,196.16 96.39,195.12 96.38,195.09 96.34,195.07 95.68,195.07 95.65,195.09 95.63,195.12
UNNAMED_2_ADLTC7878V2_I124_PHASMD on TOP: 104.39,199.85 104.41,199.88 104.44,199.9 105.36,199.9 105.4,199.88 105.41,199.85 105.41,199.19 105.4,199.15 105.36,199.14 104.44,199.14 104.41,199.15 104.39,199.19
UNNAMED_2_ADLTC7878V2_I124_SETCUR on TOP: 101.73,202.9 101.74,202.93 101.78,202.95 102.95,202.95 102.98,202.93 103,202.9 103,202.24 102.98,202.2 102.95,202.18 101.78,202.18 101.74,202.2 101.73,202.24
UNNAMED_2_ADLTC7878V2_I124_SW1 on TOP: 74.16,225.65 74.18,225.67 74.2,225.68 77.55,225.68 77.58,225.66 77.6,225.63 77.6,223.95 77.61,223.92 77.65,223.9 79.35,223.9 79.37,223.9 79.39,223.92 79.87,224.39 79.88,224.41 79.9,224.41 80.64,224.41 80.64,227.2 83.06,227.2 83.06,215.52 73.66,215.52 73.66,216.79 73.66,219.58 73.66,223.63 73.66,223.67 73.66,224.74 73.67,224.78 74.04,224.96 74.17,225.3 74.15,225.42 74.11,225.53 74.11,225.54 74.11,225.57
UNNAMED_2_ADLTC7878V2_I124_SW1 on TOP: 94.61,210.52 94.63,210.55 94.67,210.57 95.77,210.57 95.81,210.55 95.82,210.52 95.82,209.73 95.81,209.69 95.77,209.68 94.89,209.68 94.87,209.68 94.85,209.69 94.63,209.92 94.62,209.93 94.61,209.95
UNNAMED_2_ADLTC7878V2_I124_SW1 on TOP: 93.34,208.1 93.36,208.14 93.4,208.15 94.75,208.15 94.79,208.14 94.8,208.1 94.8,207.5 94.81,207.48 94.82,207.46 94.85,207.43 94.87,207.41 94.87,207.39 94.87,207.32 94.85,207.28 94.82,207.26 93.85,207.26 93.83,207.27 93.82,207.28 93.72,207.38 93.7,207.39 93.68,207.39 93.4,207.39 93.36,207.41 93.34,207.44
UNNAMED_2_ADLTC7878V2_I124_SW1 on BOTTOM: 75.31,225.63 75.33,225.66 75.36,225.68 78.71,225.68 78.73,225.67 78.75,225.65 78.8,225.57 78.8,225.54 78.8,225.53 78.75,225.42 78.74,225.3 78.89,224.94 79.25,224.79 79.42,224.82 79.57,224.91 79.59,224.92 79.63,224.92 82.8,224.92 82.8,215.57 82.79,215.53 82.75,215.52 73.84,215.52 73.8,215.53 73.79,215.57 73.79,223.85 73.8,223.89 73.84,223.9 75.26,223.9 75.3,223.92 75.31,223.95
UNNAMED_2_ADLTC7878V2_I124_SW1 on LAYER_2: 71.37,223.9 71.37,214.88 79.38,214.88 79.38,223.9
UNNAMED_2_ADLTC7878V2_I124_SW1 on LAYER_3, LAYER_7: 79.38,214.76 79.38,223.52 71.63,223.52 71.63,214.76
UNNAMED_2_ADLTC7878V2_I124_SW1 on LAYER_4, LAYER_5, LAYER_6: 79.38,214.76 79.38,223.77 71.63,223.77 71.63,214.76
UNNAMED_2_ADLTC7878V2_I124_SW2 on TOP: 113.28,232.92 113.28,224.03 115.32,224.03 115.32,220.34 113.54,220.35 113.54,220.34 113.28,220.34 113.28,218.82 106.05,218.82 106.05,215.52 97.41,215.52 97.41,232.92
UNNAMED_2_ADLTC7878V2_I124_SW2 on TOP: 99.44,209.6 99.43,209.56 99.39,209.55 98.73,209.55 98.69,209.56 98.68,209.6 98.68,211.02 98.69,211.06 98.73,211.07 99.39,211.07 99.43,211.06 99.44,211.02
UNNAMED_2_ADLTC7878V2_I124_SW2 on TOP: 94.52,196.21 94.54,196.22 95.33,196.22 95.36,196.2 95.38,196.16 95.38,194.87 95.36,194.83 95.33,194.82 94.54,194.82 94.5,194.83 94.49,194.87 94.49,196.16 94.49,196.18
UNNAMED_2_ADLTC7878V2_I124_SW2 on BOTTOM: 113.28,232.92 113.28,222.88 115.32,222.88 115.32,219.46 114.68,218.82 106.93,218.82 106.93,215.52 97.41,215.52 97.41,232.92
UNNAMED_2_ADLTC7878V2_I124_SW2 on LAYER_2, LAYER_3, LAYER_5, LAYER_6, LAYER_7: 105.28,228.09 105.28,219.07 113.28,219.07 113.28,228.09
UNNAMED_2_ADLTC7878V2_I124_SW2 on LAYER_4: 107.7,224.41 107.7,216.92 113.28,216.92 113.28,224.41
UNNAMED_2_ADLTC7878V2_I124_TG1 on TOP: 79.5,227.15 79.52,227.19 79.55,227.2 80.21,227.2 80.25,227.19 80.26,227.15 80.26,225.98 80.25,225.95 80.21,225.93 79.55,225.93 79.52,225.95 79.5,225.98
UNNAMED_2_ADLTC7878V2_I124_TG2 on TOP: 113.67,227.15 113.68,227.19 113.72,227.2 114.38,227.2 114.41,227.19 114.43,227.15 114.43,225.98 114.41,225.95 114.38,225.93 113.72,225.93 113.68,225.95 113.67,225.98
UNNAMED_2_CAP_I32_N1 on TOP: 97.66,192.61 97.68,192.64 97.71,192.66 99.39,192.66 99.43,192.64 99.44,192.61 99.44,191.82 99.43,191.78 99.39,191.77 97.71,191.77 97.68,191.78 97.66,191.82
UNNAMED_2_CAP_I92_N2 on TOP: 105.78,207.26 107.58,207.26
UNNAMED_2_CAP_I92_N2 on TOP: 104.52,205.99 104.52,204.22 105.41,204.22 105.41,205.1 106.43,205.1 106.43,205.99
UNNAMED_2_IND_I83_N1 on TOP: 95.76,232.92 95.76,215.57 95.74,215.53 95.71,215.52 83.44,215.52 83.44,232.92
UNNAMED_2_IND_I83_N1 on TOP: 96.2,210.9 96.22,210.93 96.25,210.95 96.85,210.95 96.89,210.93 96.9,210.9 96.9,209.86 96.89,209.82 96.85,209.8 96.25,209.8 96.22,209.82 96.2,209.86
UNNAMED_2_IND_I83_N1 on BOTTOM: 95.76,232.92 95.76,215.52 83.44,215.52 83.44,232.92
UNNAMED_2_NCTESTPAD_I104_N1 on TOP: 105.76,194.18 107.6,194.18
UNNAMED_2_RES_I64_N1 on TOP: 72.01,219.28 72.02,219.31 72.06,219.33 73.36,219.33 73.39,219.31 73.41,219.28 73.41,217.09 73.39,217.06 73.36,217.04 72.06,217.04 72.02,217.06 72.01,217.09
UNNAMED_2_RES_I78_N1 on TOP: 112.01,218.39 112.03,218.43 112.06,218.44 113.26,218.44 113.28,218.44 113.3,218.43 113.52,218.2 113.53,218.18 113.54,218.16 113.54,217.22 113.52,217.18 113.49,217.17 112.06,217.17 112.03,217.18 112.01,217.22
UNNAMED_2_RES_I106_N1 on TOP: 114.38,225.68 114.41,225.66 114.43,225.63 114.43,224.46 114.41,224.42 114.38,224.41 113.72,224.41 113.68,224.42 113.67,224.46 113.67,225.63 113.68,225.66 113.72,225.68
UNNAMED_2_RES_I106_N1 on TOP: 115.14,220.09 115.17,220.08 115.19,220.04 115.19,219.48 115.19,219.46 115.17,219.44 114.31,218.58 114.3,218.57 114.28,218.57 113.84,218.57 113.81,218.58 113.79,218.62 113.79,220.04 113.81,220.08 113.84,220.09
UNNAMED_3_ADLTC7878V2_I47_BG1 on TOP: 73.1,155.83 73.14,155.81 73.15,155.78 73.15,154.61 73.14,154.57 73.1,154.56 72.19,154.56 72.15,154.57 72.14,154.61 72.14,155.78 72.15,155.81 72.19,155.83
UNNAMED_3_ADLTC7878V2_I47_BG2 on TOP: 106.48,154.56 106.44,154.57 106.43,154.61 106.43,155.78 106.44,155.81 106.48,155.83 107.14,155.83 107.17,155.81 107.19,155.78 107.19,154.61 107.17,154.57 107.14,154.56
UNNAMED_3_ADLTC7878V2_I47_BOOST1 on TOP: 92.2,146.13 92.22,146.16 92.25,146.18 93.58,146.18 93.6,146.17 93.61,146.16 93.71,146.06 93.73,146.05 93.75,146.05 94.49,146.05 94.51,146.05 94.53,146.04 94.73,145.84 94.74,145.82 94.74,145.8 94.74,145.21 94.73,145.18 94.69,145.16 94.13,145.16 94.11,145.16 94.09,145.18 93.87,145.4 93.85,145.41 93.83,145.41 92.25,145.41 92.22,145.43 92.2,145.47
UNNAMED_3_ADLTC7878V2_I47_CSN on TOP: 102.86,146.3 104.66,146.3
UNNAMED_3_ADLTC7878V2_I47_CSP on TOP: 104.27,144.02 104.27,142.24 102.11,142.24 101.73,142.62 101.73,143.26 102.11,143.64 103.38,143.64 103.38,144.02
UNNAMED_3_ADLTC7878V2_I47_EXTVCC on TOP: 77.31,141.22 79.16,141.22
UNNAMED_3_ADLTC7878V2_I47_EXTVCC on TOP: 89.41,140.28 89.42,140.32 89.46,140.34 91.13,140.34 91.15,140.33 91.17,140.32 91.3,140.19 91.31,140.18 91.31,140.16 91.31,139.32 90.81,138.81 90.81,137.79 90.04,137.79 90.04,138.81 89.46,138.81 89.42,138.83 89.41,138.86
UNNAMED_3_ADLTC7878V2_I47_ISNSD on TOP: 95.83,147.32 95.87,147.31 95.89,147.27 95.89,146.23 95.87,146.19 95.83,146.18 95.53,146.18 95.51,146.18 95.49,146.19 95.07,146.61 95.06,146.62 95.06,146.64 95.06,147.27 95.07,147.31 95.11,147.32
UNNAMED_3_ADLTC7878V2_I47_ITHB on TOP: 97.66,135.2 97.68,135.24 97.71,135.25 98.37,135.25 98.41,135.24 98.42,135.2 98.42,134.39 98.42,134.37 98.41,134.36 98.18,134.13 98.17,134.12 98.15,134.11 97.71,134.11 97.68,134.13 97.66,134.16
UNNAMED_3_ADLTC7878V2_I47_MODE on TOP: 104.39,137.87 104.41,137.91 104.44,137.92 105.36,137.92 105.4,137.91 105.41,137.87 105.41,137.27 105.4,137.24 105.36,137.22 104.44,137.22 104.41,137.24 104.39,137.27
UNNAMED_3_ADLTC7878V2_I47_PGOOD on TOP: 95.63,135.2 95.65,135.24 95.68,135.25 96.34,135.25 96.38,135.24 96.39,135.2 96.39,134.16 96.38,134.13 96.34,134.11 95.68,134.11 95.65,134.13 95.63,134.16
UNNAMED_3_ADLTC7878V2_I47_PGOOD on TOP: 77.18,132.72 79.03,132.72
UNNAMED_3_ADLTC7878V2_I47_PHASMD on TOP: 104.39,138.89 104.41,138.92 104.44,138.94 105.36,138.94 105.4,138.92 105.41,138.89 105.41,138.23 105.4,138.19 105.36,138.18 104.44,138.18 104.41,138.19 104.39,138.23
UNNAMED_3_ADLTC7878V2_I47_SETCUR on TOP: 101.73,141.94 101.74,141.97 101.78,141.99 102.95,141.99 102.98,141.97 103,141.94 103,141.28 102.98,141.24 102.95,141.22 101.78,141.22 101.74,141.24 101.73,141.28
UNNAMED_3_ADLTC7878V2_I47_SW1 on TOP: 93.34,147.14 93.36,147.18 93.4,147.19 94.75,147.19 94.79,147.18 94.8,147.14 94.8,146.54 94.81,146.52 94.82,146.5 94.85,146.47 94.87,146.45 94.87,146.43 94.87,146.36 94.85,146.32 94.82,146.3 93.85,146.3 93.83,146.31 93.82,146.32 93.72,146.42 93.7,146.43 93.68,146.43 93.4,146.43 93.36,146.45 93.34,146.48
UNNAMED_3_ADLTC7878V2_I47_SW1 on TOP: 74.16,164.69 74.18,164.71 74.2,164.72 77.55,164.72 77.58,164.7 77.6,164.67 77.6,162.99 77.61,162.96 77.65,162.94 79.35,162.94 79.37,162.94 79.39,162.96 79.87,163.43 79.88,163.45 79.9,163.45 80.64,163.45 80.64,166.24 82.93,166.24 82.93,154.56 73.66,154.56 73.66,155.83 73.66,158.62 73.66,162.67 73.66,162.71 73.66,163.78 73.67,163.82 74.04,164 74.17,164.34 74.15,164.46 74.11,164.57 74.11,164.58 74.11,164.61
UNNAMED_3_ADLTC7878V2_I47_SW1 on TOP: 94.61,149.56 94.63,149.59 94.67,149.61 95.77,149.61 95.81,149.59 95.82,149.56 95.82,148.77 95.81,148.73 95.77,148.72 94.89,148.72 94.87,148.72 94.85,148.73 94.63,148.96 94.62,148.97 94.61,148.99
UNNAMED_3_ADLTC7878V2_I47_SW1 on BOTTOM: 75.31,164.67 75.33,164.7 75.36,164.72 78.71,164.72 78.73,164.71 78.75,164.69 78.8,164.61 78.8,164.58 78.8,164.57 78.75,164.46 78.74,164.34 78.89,163.98 79.25,163.83 79.42,163.86 79.57,163.95 79.59,163.96 79.63,163.96 82.93,163.96 82.93,154.56 73.84,154.56 73.8,154.57 73.79,154.61 73.79,162.89 73.8,162.93 73.84,162.94 75.26,162.94 75.3,162.96 75.31,162.99
UNNAMED_3_ADLTC7878V2_I47_SW1 on LAYER_2: 71.37,162.94 71.37,153.92 79.38,153.92 79.38,162.94
UNNAMED_3_ADLTC7878V2_I47_SW1 on LAYER_3, LAYER_7: 79.38,153.8 79.38,162.56 71.63,162.56 71.63,153.8
UNNAMED_3_ADLTC7878V2_I47_SW1 on LAYER_4, LAYER_5, LAYER_6: 79.38,153.8 79.38,162.81 71.63,162.81 71.63,153.8
UNNAMED_3_ADLTC7878V2_I47_SW2 on TOP: 113.28,172.09 113.28,163.07 115.32,163.07 115.32,159.38 113.54,159.39 113.54,159.38 113.28,159.38 113.28,157.86 106.05,157.86 106.05,154.56 97.41,154.56 97.41,172.09
UNNAMED_3_ADLTC7878V2_I47_SW2 on TOP: 94.52,135.25 94.54,135.25 95.33,135.25 95.36,135.24 95.38,135.2 95.38,133.91 95.36,133.87 95.33,133.86 94.54,133.86 94.5,133.87 94.49,133.91 94.49,135.2 94.49,135.22
UNNAMED_3_ADLTC7878V2_I47_SW2 on TOP: 99.44,148.64 99.43,148.6 99.39,148.59 98.73,148.59 98.69,148.6 98.68,148.64 98.68,150.06 98.69,150.1 98.73,150.11 99.39,150.11 99.43,150.1 99.44,150.06
UNNAMED_3_ADLTC7878V2_I47_SW2 on BOTTOM: 113.28,172.09 113.28,161.93 115.32,161.93 115.32,158.5 114.68,157.86 106.93,157.86 106.93,154.56 97.41,154.56 97.41,172.09
UNNAMED_3_ADLTC7878V2_I47_SW2 on LAYER_2, LAYER_3, LAYER_5, LAYER_6, LAYER_7: 105.28,167.13 105.28,158.12 113.28,158.12 113.28,167.13
UNNAMED_3_ADLTC7878V2_I47_SW2 on LAYER_4: 107.7,163.45 107.7,155.96 113.28,155.96 113.28,163.45
UNNAMED_3_ADLTC7878V2_I47_TG1 on TOP: 79.5,166.19 79.52,166.23 79.55,166.24 80.21,166.24 80.25,166.23 80.26,166.19 80.26,165.02 80.25,164.99 80.21,164.97 79.55,164.97 79.52,164.99 79.5,165.02
UNNAMED_3_ADLTC7878V2_I47_TG2 on TOP: 113.67,166.19 113.68,166.23 113.72,166.24 114.38,166.24 114.41,166.23 114.43,166.19 114.43,165.02 114.41,164.99 114.38,164.97 113.72,164.97 113.68,164.99 113.67,165.02
UNNAMED_3_ADLTC7878V2_I47_VOUT on TOP: 99.19,146.63 99.2,146.67 99.24,146.69 100.66,146.69 100.7,146.67 100.71,146.63 100.71,145.85 100.7,145.81 100.66,145.8 99.24,145.8 99.2,145.81 99.19,145.85
UNNAMED_3_CAP_I32_N1 on TOP: 97.66,131.65 97.68,131.68 97.71,131.7 99.39,131.7 99.43,131.68 99.44,131.65 99.44,130.86 99.43,130.82 99.39,130.81 97.71,130.81 97.68,130.82 97.66,130.86
UNNAMED_3_CAP_I94_N2 on TOP: 105.78,146.3 107.58,146.3
UNNAMED_3_CAP_I94_N2 on TOP: 104.52,145.03 104.52,143.26 105.41,143.26 105.41,144.15 106.43,144.15 106.43,145.03
UNNAMED_3_IND_I85_N1 on TOP: 96.2,149.94 96.22,149.97 96.25,149.99 96.85,149.99 96.89,149.97 96.9,149.94 96.9,148.9 96.89,148.86 96.85,148.84 96.25,148.84 96.22,148.86 96.2,148.9
UNNAMED_3_IND_I85_N1 on TOP, BOTTOM: 95.76,172.09 95.76,154.56 83.44,154.56 83.44,172.09
UNNAMED_3_NCTESTPAD_I107_N1 on TOP: 105.76,133.22 107.6,133.22
UNNAMED_3_RES_I66_N1 on TOP: 72.01,158.32 72.02,158.35 72.06,158.37 73.36,158.37 73.39,158.35 73.41,158.32 73.41,156.13 73.39,156.1 73.36,156.08 72.06,156.08 72.02,156.1 72.01,156.13
UNNAMED_3_RES_I80_N1 on TOP: 112.01,157.43 112.03,157.47 112.06,157.48 113.26,157.48 113.28,157.48 113.3,157.47 113.52,157.24 113.53,157.22 113.54,157.2 113.54,156.26 113.52,156.22 113.49,156.21 112.06,156.21 112.03,156.22 112.01,156.26
UNNAMED_3_RES_I109_N1 on TOP: 115.14,159.13 115.17,159.12 115.19,159.08 115.19,158.52 115.19,158.5 115.17,158.48 114.31,157.62 114.3,157.61 114.28,157.61 113.84,157.61 113.81,157.62 113.79,157.66 113.79,159.08 113.81,159.12 113.84,159.13
UNNAMED_3_RES_I109_N1 on TOP: 114.38,164.72 114.41,164.7 114.43,164.67 114.43,163.5 114.41,163.46 114.38,163.45 113.72,163.45 113.68,163.46 113.67,163.5 113.67,164.67 113.68,164.7 113.72,164.72
UNNAMED_4_ADLTC7878V2_I126_BG1 on TOP: 73.1,94.87 73.14,94.85 73.15,94.82 73.15,93.65 73.14,93.61 73.1,93.6 72.19,93.6 72.15,93.61 72.14,93.65 72.14,94.82 72.15,94.85 72.19,94.87
UNNAMED_4_ADLTC7878V2_I126_BG2 on TOP: 106.48,93.6 106.44,93.61 106.43,93.65 106.43,94.82 106.44,94.85 106.48,94.87 107.14,94.87 107.17,94.85 107.19,94.82 107.19,93.65 107.17,93.61 107.14,93.6
UNNAMED_4_ADLTC7878V2_I126_BOOST1 on TOP: 92.2,85.17 92.22,85.2 92.25,85.22 93.58,85.22 93.6,85.21 93.61,85.2 93.71,85.1 93.73,85.09 93.75,85.09 94.49,85.09 94.51,85.09 94.53,85.08 94.73,84.88 94.74,84.86 94.74,84.84 94.74,84.25 94.73,84.22 94.69,84.2 94.13,84.2 94.11,84.2 94.09,84.22 93.87,84.44 93.85,84.45 93.83,84.45 92.25,84.45 92.22,84.47 92.2,84.51
UNNAMED_4_ADLTC7878V2_I126_CSN on TOP: 102.86,85.34 104.66,85.34
UNNAMED_4_ADLTC7878V2_I126_CSP on TOP: 104.27,83.06 104.27,81.28 102.11,81.28 101.73,81.66 101.73,82.3 102.11,82.68 103.38,82.68 103.38,83.06
UNNAMED_4_ADLTC7878V2_I126_EXTVCC on TOP: 89.41,79.32 89.42,79.36 89.46,79.38 91.13,79.38 91.15,79.37 91.17,79.36 91.3,79.23 91.31,79.22 91.31,79.2 91.31,78.23 90.81,77.72 90.81,76.83 90.04,76.83 90.04,77.85 89.46,77.85 89.42,77.87 89.41,77.9
UNNAMED_4_ADLTC7878V2_I126_EXTVCC on TOP: 77.31,80.26 79.16,80.26
UNNAMED_4_ADLTC7878V2_I126_ISNSD on TOP: 95.83,86.36 95.87,86.35 95.89,86.31 95.89,85.27 95.87,85.23 95.83,85.22 95.53,85.22 95.51,85.22 95.49,85.23 95.07,85.65 95.06,85.66 95.06,85.68 95.06,86.31 95.07,86.35 95.11,86.36
UNNAMED_4_ADLTC7878V2_I126_ITHB on TOP: 97.66,74.24 97.68,74.28 97.71,74.3 98.37,74.3 98.41,74.28 98.42,74.24 98.42,73.43 98.42,73.41 98.41,73.4 98.18,73.17 98.17,73.16 98.15,73.15 97.71,73.15 97.68,73.17 97.66,73.2
UNNAMED_4_ADLTC7878V2_I126_MODE on TOP: 104.39,76.91 104.41,76.95 104.44,76.96 105.36,76.96 105.4,76.95 105.41,76.91 105.41,76.31 105.4,76.28 105.36,76.26 104.44,76.26 104.41,76.28 104.39,76.31
UNNAMED_4_ADLTC7878V2_I126_PGOOD on TOP: 95.63,74.24 95.65,74.28 95.68,74.3 96.34,74.3 96.38,74.28 96.39,74.24 96.39,73.2 96.38,73.17 96.34,73.15 95.68,73.15 95.65,73.17 95.63,73.2
UNNAMED_4_ADLTC7878V2_I126_PGOOD on TOP: 77.18,71.12 79.03,71.12
UNNAMED_4_ADLTC7878V2_I126_PHASMD on TOP: 104.39,77.93 104.41,77.96 104.44,77.98 105.36,77.98 105.4,77.96 105.41,77.93 105.41,77.27 105.4,77.23 105.36,77.22 104.44,77.22 104.41,77.23 104.39,77.27
UNNAMED_4_ADLTC7878V2_I126_SETCUR on TOP: 101.73,80.98 101.74,81.01 101.78,81.03 102.95,81.03 102.98,81.01 103,80.98 103,80.32 102.98,80.28 102.95,80.26 101.78,80.26 101.74,80.28 101.73,80.32
UNNAMED_4_ADLTC7878V2_I126_SW1 on TOP: 93.34,86.18 93.36,86.22 93.4,86.23 94.75,86.23 94.79,86.22 94.8,86.18 94.8,85.58 94.81,85.56 94.82,85.54 94.85,85.51 94.87,85.49 94.87,85.47 94.87,85.4 94.85,85.36 94.82,85.34 93.85,85.34 93.83,85.35 93.82,85.36 93.72,85.46 93.7,85.47 93.68,85.47 93.4,85.47 93.36,85.49 93.34,85.52
UNNAMED_4_ADLTC7878V2_I126_SW1 on TOP: 94.61,88.6 94.63,88.63 94.67,88.65 95.77,88.65 95.81,88.63 95.82,88.6 95.82,87.81 95.81,87.77 95.77,87.76 94.89,87.76 94.87,87.76 94.85,87.77 94.63,88 94.62,88.01 94.61,88.03
UNNAMED_4_ADLTC7878V2_I126_SW1 on TOP: 74.16,103.73 74.18,103.75 74.2,103.76 77.55,103.76 77.58,103.74 77.6,103.71 77.6,102.03 77.61,102 77.65,101.98 79.35,101.98 79.37,101.98 79.39,102 79.87,102.47 79.88,102.49 79.9,102.49 80.52,102.49 80.52,105.28 82.93,105.28 82.93,93.6 73.66,93.6 73.66,94.87 73.66,97.66 73.66,101.71 73.66,101.75 73.66,102.82 73.67,102.86 74.04,103.04 74.17,103.38 74.15,103.5 74.11,103.61 74.11,103.62 74.11,103.65
UNNAMED_4_ADLTC7878V2_I126_SW1 on BOTTOM: 75.31,103.71 75.33,103.74 75.36,103.76 78.71,103.76 78.73,103.75 78.75,103.73 78.8,103.65 78.8,103.62 78.8,103.61 78.75,103.5 78.74,103.38 78.89,103.02 79.25,102.87 79.42,102.9 79.57,102.99 79.59,103 79.63,103 82.93,103 82.93,93.6 73.84,93.6 73.8,93.61 73.79,93.65 73.79,101.93 73.8,101.97 73.84,101.98 75.26,101.98 75.3,102 75.31,102.03
UNNAMED_4_ADLTC7878V2_I126_SW1 on LAYER_2: 71.37,101.98 71.37,92.96 79.38,92.96 79.38,101.98
UNNAMED_4_ADLTC7878V2_I126_SW1 on LAYER_3, LAYER_7: 79.38,92.84 79.38,101.6 71.63,101.6 71.63,92.84
UNNAMED_4_ADLTC7878V2_I126_SW1 on LAYER_4, LAYER_5, LAYER_6: 79.38,92.84 79.38,101.85 71.63,101.85 71.63,92.84
UNNAMED_4_ADLTC7878V2_I126_SW2 on TOP: 113.28,111.12 113.28,102.11 115.32,102.11 115.32,98.42 113.54,98.43 113.54,98.42 113.28,98.42 113.28,96.9 106.05,96.9 106.05,93.6 97.41,93.6 97.41,111.12
UNNAMED_4_ADLTC7878V2_I126_SW2 on TOP: 99.44,87.68 99.43,87.64 99.39,87.63 98.73,87.63 98.69,87.64 98.68,87.68 98.68,89.1 98.69,89.14 98.73,89.15 99.39,89.15 99.43,89.14 99.44,89.1
UNNAMED_4_ADLTC7878V2_I126_SW2 on TOP: 94.52,74.29 94.54,74.3 95.33,74.3 95.36,74.28 95.38,74.24 95.38,72.95 95.36,72.91 95.33,72.9 94.54,72.9 94.5,72.91 94.49,72.95 94.49,74.24 94.49,74.26
UNNAMED_4_ADLTC7878V2_I126_SW2 on BOTTOM: 113.28,111.12 113.28,100.97 115.32,100.97 115.32,97.54 114.68,96.9 106.93,96.9 106.93,93.6 97.41,93.6 97.41,111.12
UNNAMED_4_ADLTC7878V2_I126_SW2 on LAYER_2, LAYER_3, LAYER_5, LAYER_6, LAYER_7: 105.28,106.17 105.28,97.16 113.28,97.16 113.28,106.17
UNNAMED_4_ADLTC7878V2_I126_SW2 on LAYER_4: 107.7,102.49 107.7,95 113.28,95 113.28,102.49
UNNAMED_4_ADLTC7878V2_I126_TG1 on TOP: 79.5,105.23 79.52,105.27 79.55,105.28 80.21,105.28 80.25,105.27 80.26,105.23 80.26,104.06 80.25,104.03 80.21,104.01 79.55,104.01 79.52,104.03 79.5,104.06
UNNAMED_4_ADLTC7878V2_I126_TG2 on TOP: 113.67,105.23 113.68,105.27 113.72,105.28 114.38,105.28 114.41,105.27 114.43,105.23 114.43,104.06 114.41,104.03 114.38,104.01 113.72,104.01 113.68,104.03 113.67,104.06
UNNAMED_4_ADLTC7878V2_I126_VOUT on TOP: 99.19,85.67 99.2,85.71 99.24,85.72 100.66,85.72 100.7,85.71 100.71,85.67 100.71,84.89 100.7,84.85 100.66,84.84 99.24,84.84 99.2,84.85 99.19,84.89
UNNAMED_4_CAP_I32_N1 on TOP: 97.66,70.69 97.68,70.72 97.71,70.74 99.39,70.74 99.43,70.72 99.44,70.69 99.44,69.9 99.43,69.86 99.39,69.85 97.71,69.85 97.68,69.86 97.66,69.9
UNNAMED_4_CAP_I93_N2 on TOP: 104.52,84.07 104.52,82.3 105.41,82.3 105.41,83.19 106.43,83.19 106.43,84.07
UNNAMED_4_CAP_I93_N2 on TOP: 105.78,85.34 107.58,85.34
